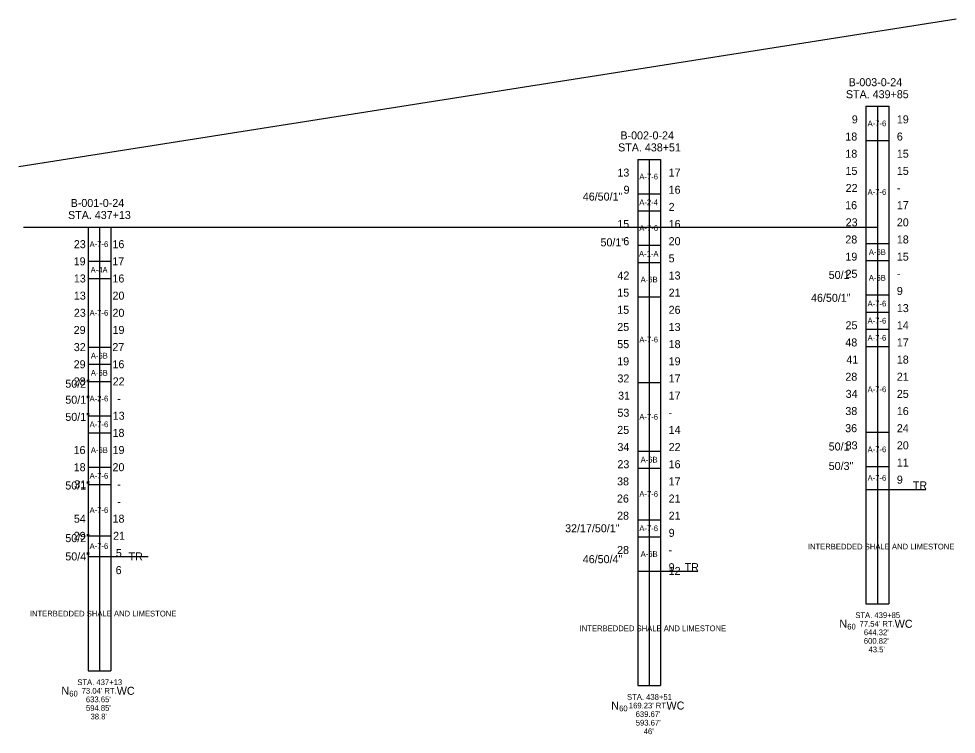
# Model space of a CAD drawing. Extents: x 5.7 to 93.8, y -5.1 to 22.
# Drawn here: x 77.37 to 93.77, y 5.93 to 18.44 of the extents above; entities that cross this region are included whole.
import ezdxf

# ---------------------------------------------------------------- set-up
doc = ezdxf.new("R2010")
doc.units = 0
for name, color, linetype in [('Default', 7, 'Continuous'), ('GT_Project_Soil_Boring', 7, 'Continuous'), ('GT_Project_Text', 7, 'Continuous'), ('GT_Project_Text_3', 7, 'Continuous'), ('SC_Scratch1', 7, 'Continuous'), ('SC_Scratch2', 7, 'Continuous')]:
    doc.layers.add(name, color=color, linetype=linetype)

msp = doc.modelspace()

# ---------------------------------------------------------------- linework, layer by layer
at = {"layer": 'Default'}
msp.add_line((77.367, 15.862), (93.767, 18.443), dxfattribs=at)
at = {"layer": 'GT_Project_Soil_Boring'}
for p, q in [((92.188, 16.913), (92.588, 16.913)), ((92.188, 16.913), (92.188, 8.213)), ((92.388, 16.913), (92.388, 8.213)), ((92.588, 16.913), (92.588, 8.213)), ((92.188, 16.313), (92.588, 16.313)), ((88.196, 15.983), (88.596, 15.983)), ((88.196, 15.983), (88.196, 6.783)), ((88.396, 15.983), (88.396, 6.783)), ((88.596, 15.983), (88.596, 6.783)), ((88.196, 15.383), (88.596, 15.383)), ((88.196, 15.083), (88.596, 15.083)), ((78.579, 14.801), (78.979, 14.801)), ((78.579, 14.801), (78.579, 7.041)), ((78.779, 14.801), (78.779, 7.041)), ((78.979, 14.801), (78.979, 7.041)), ((88.196, 14.483), (88.596, 14.483)), ((92.188, 14.513), (92.588, 14.513)), ((78.579, 14.201), (78.979, 14.201)), ((88.196, 14.183), (88.596, 14.183)), ((92.188, 14.213), (92.588, 14.213)), ((78.579, 13.901), (78.979, 13.901)), ((92.188, 13.613), (92.588, 13.613)), ((88.196, 13.583), (88.596, 13.583)), ((92.188, 13.313), (92.588, 13.313)), ((92.188, 13.013), (92.588, 13.013)), ((78.579, 12.701), (78.979, 12.701)), ((92.188, 12.713), (92.588, 12.713)), ((78.579, 12.401), (78.979, 12.401)), ((78.579, 12.101), (78.979, 12.101)), ((88.196, 12.083), (88.596, 12.083)), ((78.579, 11.501), (78.979, 11.501)), ((78.579, 11.201), (78.979, 11.201)), ((92.188, 11.213), (92.588, 11.213)), ((88.196, 10.883), (88.596, 10.883)), ((78.579, 10.601), (78.979, 10.601)), ((88.196, 10.583), (88.596, 10.583)), ((92.188, 10.613), (92.588, 10.613)), ((78.579, 10.301), (78.979, 10.301)), ((92.188, 10.213), (92.588, 10.213)), ((88.196, 9.683), (88.596, 9.683)), ((78.579, 9.401), (78.979, 9.401)), ((88.196, 9.383), (88.596, 9.383)), ((78.579, 9.041), (78.979, 9.041)), ((88.196, 8.783), (88.596, 8.783)), ((92.188, 8.213), (92.588, 8.213)), ((78.579, 7.041), (78.979, 7.041)), ((88.196, 6.783), (88.596, 6.783))]:
    msp.add_line(p, q, dxfattribs=at)
at = {"layer": 'GT_Project_Text'}
for p, q in [((92.588, 10.213), (93.238, 10.213)), ((78.979, 9.041), (79.629, 9.041)), ((88.596, 8.783), (89.246, 8.783)), ((91.861, 7.863), (91.861, 7.863)), ((78.251, 6.691), (78.251, 6.691)), ((87.869, 6.433), (87.869, 6.433))]:
    msp.add_line(p, q, dxfattribs=at)
at = {"layer": 'SC_Scratch1'}
msp.add_lwpolyline([(77.448, 14.801), (78.779, 14.801), (88.396, 14.801), (92.388, 14.801)], dxfattribs=at)

# ---------------------------------------------------------------- texts
at = {"layer": 'GT_Project_Text'}
for s, height, p in [('B-003-0-24', 0.14, (91.885, 17.263)), ('9', 0.14, (91.94, 16.613)), ('19', 0.14, (92.728, 16.613)), ('B-002-0-24', 0.14, (87.892, 16.333)), ('18', 0.14, (91.827, 16.313)), ('6', 0.14, (92.728, 16.313)), ('18', 0.14, (91.827, 16.013)), ('15', 0.14, (92.728, 16.013)), ('13', 0.14, (87.84, 15.683)), ('17', 0.14, (88.736, 15.683)), ('15', 0.14, (91.83, 15.713)), ('15', 0.14, (92.728, 15.713)), ('9', 0.14, (87.947, 15.383)), ('16', 0.14, (88.736, 15.383)), ('22', 0.14, (91.832, 15.413)), ('-', 0.14, (92.728, 15.413)), ('B-001-0-24', 0.14, (78.275, 15.151)), ('46/50/1"', 0.14, (87.234, 15.263)), ('16', 0.14, (91.824, 15.113)), ('17', 0.14, (92.728, 15.113)), ('2', 0.14, (88.736, 15.083)), ('16', 0.14, (88.736, 14.783)), ('23', 0.14, (91.833, 14.813)), ('20', 0.14, (92.728, 14.813)), ('15', 0.14, (87.837, 14.783)), ('50/1"', 0.14, (87.544, 14.463)), ('6', 0.14, (87.943, 14.483)), ('20', 0.14, (88.736, 14.483)), ('28', 0.14, (91.827, 14.513)), ('18', 0.14, (92.728, 14.513)), ('23', 0.14, (78.331, 14.431)), ('16', 0.14, (79.006, 14.431)), ('19', 0.14, (78.328, 14.131)), ('17', 0.14, (79.004, 14.131)), ('5', 0.14, (88.736, 14.183)), ('19', 0.14, (91.828, 14.213)), ('15', 0.14, (92.728, 14.213)), ('13', 0.14, (78.331, 13.831)), ('16', 0.14, (79.006, 13.831)), ('42', 0.14, (87.84, 13.883)), ('13', 0.14, (88.736, 13.883)), ('50/1"', 0.14, (91.536, 13.893)), ('25', 0.14, (91.83, 13.913)), ('-', 0.14, (92.728, 13.913)), ('13', 0.14, (78.331, 13.531)), ('20', 0.14, (79.007, 13.531)), ('15', 0.14, (87.837, 13.583)), ('21', 0.14, (88.736, 13.583)), ('46/50/1"', 0.14, (91.227, 13.493)), ('9', 0.14, (92.728, 13.613)), ('13', 0.14, (92.728, 13.313)), ('23', 0.14, (78.331, 13.231)), ('20', 0.14, (79.007, 13.231)), ('15', 0.14, (87.837, 13.283)), ('26', 0.14, (88.736, 13.283)), ('25', 0.14, (87.837, 12.983)), ('13', 0.14, (88.736, 12.983)), ('25', 0.14, (91.83, 13.013)), ('14', 0.14, (92.728, 13.013)), ('29', 0.14, (78.328, 12.931)), ('19', 0.14, (79.008, 12.931)), ('55', 0.14, (87.837, 12.683)), ('18', 0.14, (88.736, 12.683)), ('48', 0.14, (91.827, 12.713)), ('17', 0.14, (92.728, 12.713)), ('32', 0.14, (78.33, 12.631)), ('27', 0.14, (79.004, 12.631)), ('29', 0.14, (78.328, 12.331)), ('16', 0.14, (79.006, 12.331)), ('19', 0.14, (87.836, 12.383)), ('19', 0.14, (88.736, 12.383)), ('41', 0.14, (91.845, 12.413)), ('18', 0.14, (92.728, 12.413)), ('50/2"', 0.14, (78.182, 11.991)), ('28', 0.14, (78.328, 12.031)), ('22', 0.14, (79.01, 12.031)), ('32', 0.14, (87.84, 12.083)), ('17', 0.14, (88.736, 12.083)), ('28', 0.14, (91.827, 12.113)), ('21', 0.14, (92.728, 12.113)), ('50/1"', 0.14, (78.182, 11.711)), ('31', 0.14, (87.852, 11.783)), ('17', 0.14, (88.736, 11.783)), ('34', 0.14, (91.833, 11.813)), ('25', 0.14, (92.728, 11.813)), ('-', 0.14, (79.088, 11.731)), ('38', 0.14, (91.827, 11.513)), ('16', 0.14, (92.728, 11.513)), ('50/1"', 0.14, (78.182, 11.411)), ('13', 0.14, (79.011, 11.431)), ('53', 0.14, (87.84, 11.483)), ('-', 0.14, (88.736, 11.483)), ('25', 0.14, (87.837, 11.183)), ('14', 0.14, (88.736, 11.183)), ('36', 0.14, (91.824, 11.213)), ('24', 0.14, (92.728, 11.213)), ('18', 0.14, (79.008, 11.131)), ('34', 0.14, (87.84, 10.883)), ('22', 0.14, (88.736, 10.883)), ('50/1"', 0.14, (91.536, 10.893)), ('83', 0.14, (91.833, 10.913)), ('20', 0.14, (92.728, 10.913)), ('16', 0.14, (78.326, 10.831)), ('19', 0.14, (79.008, 10.831)), ('18', 0.14, (78.328, 10.531)), ('20', 0.14, (79.007, 10.531)), ('23', 0.14, (87.84, 10.583)), ('16', 0.14, (88.736, 10.583)), ('50/3"', 0.14, (91.536, 10.553)), ('11', 0.14, (92.728, 10.613)), ('50/1"', 0.14, (78.182, 10.211)), ('31', 0.14, (78.337, 10.231)), ('38', 0.14, (87.834, 10.283)), ('17', 0.14, (88.736, 10.283)), ('9', 0.14, (92.728, 10.313)), ('TR', 0.14, (93.008, 10.213)), ('-', 0.14, (79.088, 10.231)), ('26', 0.14, (87.832, 9.983)), ('21', 0.14, (88.736, 9.983)), ('-', 0.14, (79.088, 9.931)), ('54', 0.14, (78.331, 9.631)), ('18', 0.14, (79.008, 9.631)), ('28', 0.14, (87.834, 9.683)), ('21', 0.14, (88.736, 9.683)), ('32/17/50/1"', 0.14, (86.925, 9.463)), ('9', 0.14, (88.736, 9.383)), ('50/2"', 0.14, (78.182, 9.291)), ('29', 0.14, (78.328, 9.331)), ('21', 0.14, (79.017, 9.331)), ('28', 0.14, (87.834, 9.083)), ('50/4"', 0.14, (78.182, 8.971)), ('5', 0.14, (79.065, 9.031)), ('TR', 0.14, (79.288, 8.971)), ('46/50/4"', 0.14, (87.234, 8.923)), ('-', 0.14, (88.736, 9.083)), ('6', 0.14, (79.062, 8.731)), ('9', 0.14, (88.736, 8.783)), ('12', 0.14, (88.736, 8.717)), ('TR', 0.14, (89.016, 8.783)), ('N', 0.14, (91.723, 7.793)), ('WC', 0.14, (92.691, 7.793)), ('60', 0.1, (91.861, 7.763)), ('N', 0.14, (78.113, 6.621)), ('WC', 0.14, (79.082, 6.621)), ('60', 0.1, (78.251, 6.591)), ('N', 0.14, (87.731, 6.363)), ('60', 0.1, (87.869, 6.333)), ('WC', 0.14, (88.699, 6.363))]:
    msp.add_text(s, height=height, dxfattribs=at).set_placement(p)
at = {"layer": 'GT_Project_Text_3'}
for s, p in [('STA. 439+85', (91.837, 17.053)), ('STA. 438+51', (87.852, 16.123)), ('STA. 437+13', (78.229, 14.941))]:
    msp.add_text(s, height=0.14, dxfattribs=at).set_placement(p)
at = {"layer": 'SC_Scratch1'}
for s, p in [('A-7-6', (92.216, 16.563)), ('A-7-6', (88.223, 15.633)), ('A-7-6', (92.216, 15.363)), ('A-2-4', (88.222, 15.183)), ('A-7-6', (88.223, 14.733)), ('A-7-6', (78.606, 14.451)), ('A-1-A', (88.217, 14.283)), ('A-6B', (92.238, 14.313)), ('A-4A', (78.624, 14.001)), ('A-6B', (92.238, 13.863)), ('A-6B', (88.246, 13.833)), ('A-7-6', (92.216, 13.413)), ('A-7-6', (78.606, 13.251)), ('A-7-6', (92.216, 13.113)), ('A-7-6', (88.223, 12.783)), ('A-7-6', (92.216, 12.813)), ('A-6B', (78.628, 12.501)), ('A-6B', (78.628, 12.201)), ('A-7-6', (92.216, 11.913)), ('A-2-6', (78.606, 11.751)), ('A-7-6', (88.223, 11.433)), ('A-7-6', (78.606, 11.301)), ('A-6B', (78.628, 10.851)), ('A-7-6', (92.216, 10.863)), ('A-6B', (88.246, 10.683)), ('A-7-6', (78.606, 10.401)), ('A-7-6', (92.216, 10.363)), ('A-7-6', (88.223, 10.083)), ('A-7-6', (78.606, 9.801)), ('A-7-6', (88.223, 9.483)), ('A-7-6', (78.606, 9.171)), ('INTERBEDDED SHALE AND LIMESTONE', (91.171, 9.163)), ('A-6B', (88.246, 9.033)), ('INTERBEDDED SHALE AND LIMESTONE', (77.561, 7.991)), ('INTERBEDDED SHALE AND LIMESTONE', (87.179, 7.733))]:
    msp.add_text(s, height=0.1, dxfattribs=at).set_placement(p)
at = {"layer": 'SC_Scratch2'}
for s, p in [('STA. 439+85', (92.001, 7.963)), ("77.54' RT.", (92.077, 7.813)), ("644.32'", (92.151, 7.663)), ("600.82'", (92.151, 7.513)), ("43.5'", (92.233, 7.363)), ('STA. 437+13', (78.391, 6.791)), ("73.04' RT.", (78.468, 6.641)), ("633.65'", (78.542, 6.491)), ('STA. 438+51', (88.008, 6.533)), ("594.85'", (78.543, 6.341)), ("169.23' RT.", (88.04, 6.383)), ("38.8'", (78.623, 6.191)), ("639.67'", (88.159, 6.233)), ("593.67'", (88.161, 6.083)), ("46'", (88.3, 5.933))]:
    msp.add_text(s, height=0.1, dxfattribs=at).set_placement(p)

doc.saveas('drawing.dxf')
